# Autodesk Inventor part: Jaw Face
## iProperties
Created: 2002-02
Part Number: Jaw Face
Document SubType Name: Modeling
Designer: ***
Control State: 0
Master: False
Checked Out: False
Shininess: 77.0
Length Units: 11269
Angle Units: 11279
Time Units: 11290
Mass Units: 11283
Length Display Precision: 3
Angle Display Precision: 2
Compacted: True
Density: 0.0
Volumn: 0.0
Area: 0.0
PropertySet Name: Model Information
Author: ***
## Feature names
1. Extrusion1
